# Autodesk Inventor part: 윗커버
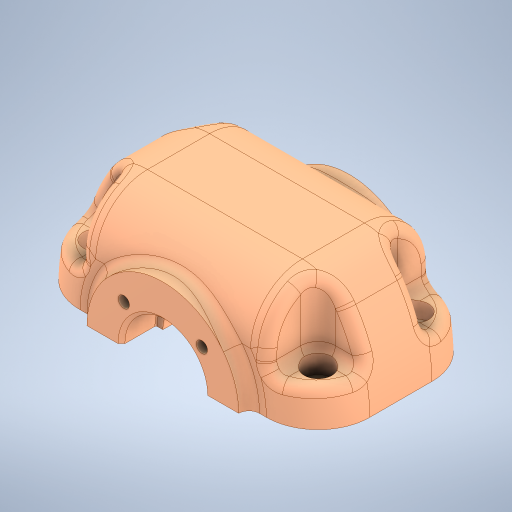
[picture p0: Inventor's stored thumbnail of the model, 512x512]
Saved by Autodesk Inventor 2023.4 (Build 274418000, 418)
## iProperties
Created: 2024-05
Part Number: 윗커버
Material: 알루미늄 6061
Document SubType Name: Modeling
Designer: user
Density: 2.7 g/cm^3
Appearance: 기본값
Sending System: Autodesk Inventor 2025
Preprocessor: ST-DEVELOPER v20
Author: jhkim
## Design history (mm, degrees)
feature "솔리드1"
node "솔리드2"
